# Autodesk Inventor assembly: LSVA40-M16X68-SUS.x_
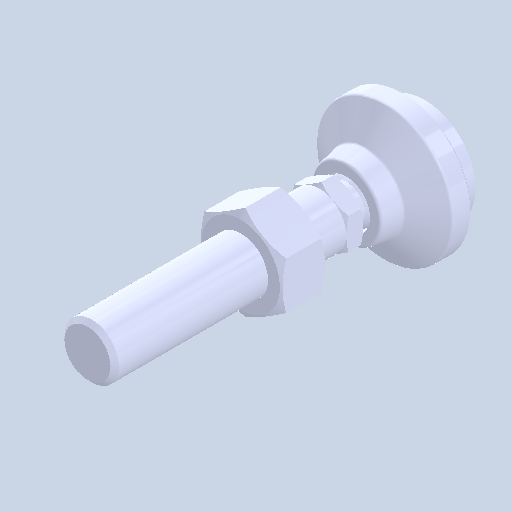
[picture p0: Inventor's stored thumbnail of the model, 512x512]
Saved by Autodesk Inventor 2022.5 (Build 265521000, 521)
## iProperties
Created: 2024-08
Part Number: LSVA40-M16X68-SUS.x_
Document SubType Name: Assembly
Designer: ImaoCorp
Author: ImaoCorp
Sending System: SOLIDWORKS 2022-2022290
MC: AMD64
MC_MODEL: Intel64 Family 6 Model 60 Stepping 3, GenuineIntel
OS: Windows_NT
FRU: Parasolid Version 33.1, build 260,  4-25-2022
FORMAT: text
GUISE: transmit
KEY: FILELSVA40-M16X68-SUS.x_t
DATE: Fri Aug 23 16:07:54 2024
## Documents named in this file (4)
- X:\14_SW2022-Inv2022\06_2024-10新製品(SME)\ELS_データ\l\lsva40-m16x68-sus\LSVA40-M16X68-SUS.x_.iam
- X:\14_SW2022-Inv2022\06_2024-10新製品(SME)\ELS_データ\l\lsva40-m16x68-sus\LSVA40-M16X68-SUS_01.ipt
- X:\14_SW2022-Inv2022\06_2024-10新製品(SME)\ELS_データ\l\lsva40-m16x68-sus\LSVA40-M16X68-SUS_02.ipt
- X:\14_SW2022-Inv2022\06_2024-10新製品(SME)\ELS_データ\l\lsva40-m16x68-sus\LSVA40-M16X68-SUS_03.ipt
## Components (3 placed, 3 different names)
1. LSVA40-M16X68-SUS_01
2. LSVA40-M16X68-SUS_02
3. LSVA40-M16X68-SUS_03
